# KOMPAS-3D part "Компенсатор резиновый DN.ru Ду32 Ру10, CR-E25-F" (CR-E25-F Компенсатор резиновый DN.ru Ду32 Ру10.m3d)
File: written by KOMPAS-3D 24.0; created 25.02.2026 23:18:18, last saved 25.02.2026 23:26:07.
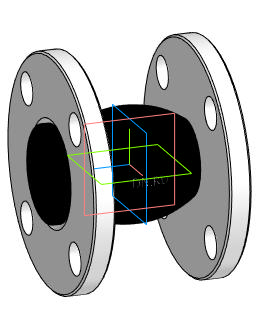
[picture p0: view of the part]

Document properties: Автор: DN.RU; Полное имя файла: D:\PROJECT CAD\DN.RU\...178(4)(ACTUALE). CR-E25-F Компенсатор резиновый DN.ru Ру10-16\DN32_PN10\CR-E25-F Компенсатор резиновый DN.ru Ду32 Ру10.m3d

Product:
- Body: Твердое тело2  | qty 1
    Масса: 2.963372
- Part/product: Компенсатор резиновый DN.ru Ду32 Ру10  | designation CR-E25-F
    Масса: 2.94
    Раздел спецификации: Прочие изделия
    Комментарий: D140-02160
    Примечание: D140-02160
    additional columns: Типовые

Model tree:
1. Твердое тело2  (labels: Твердое тело2)

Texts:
  CR-E25-F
